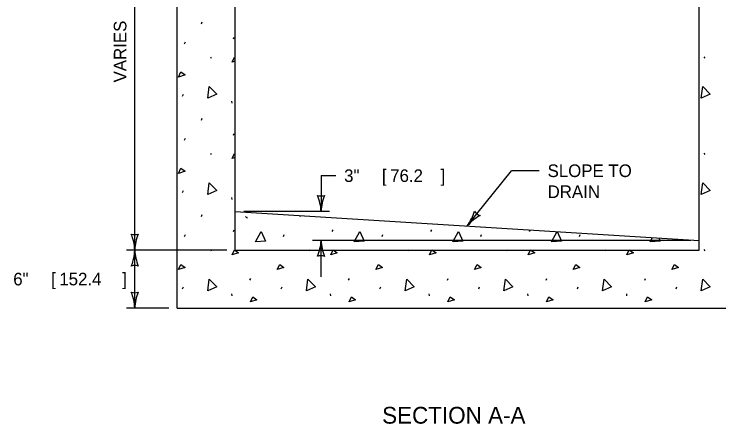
# Model space of a CAD drawing. Extents: x 49991.4 to 50057, y 49987.6 to 50011.4.
# Drawn here: x 50041.919 to 50045.28, y 49989.082 to 49991.034 of the extents above; entities that cross this region are included whole.
import ezdxf

# ---------------------------------------------------------------- set-up
doc = ezdxf.new("R2010")
doc.units = 0
for name, color, linetype in [('Level 1', 7, 'Continuous'), ('Level 2', 7, 'Continuous'), ('Level 3', 7, 'Continuous')]:
    doc.layers.add(name, color=color, linetype=linetype)

msp = doc.modelspace()

# ---------------------------------------------------------------- linework, layer by layer
at = {"layer": 'Level 1'}
for p, q in [((50042.6975, 49989.6339), (50042.6975, 49992.1229)), ((50042.974, 49989.9104), (50042.974, 49991.8463)), ((50045.1865, 49989.9104), (50045.1865, 49991.8463)), ((50042.8121, 49990.9888), (50042.8161, 49990.9976)), ((50042.7326, 49990.8933), (50042.7365, 49990.9022)), ((50042.9654, 49990.9159), (50042.9693, 49990.9248)), ((50042.8554, 49990.8305), (50042.8593, 49990.8246)), ((50045.2081, 49990.8305), (50045.2121, 49990.8246)), ((50042.974, 49990.8098), (50042.9585, 49990.8049)), ((50042.7228, 49990.6438), (50042.7267, 49990.6527)), ((50042.9563, 49990.6192), (50042.9573, 49990.6103)), ((50042.8121, 49990.5299), (50042.8161, 49990.5387)), ((50042.9654, 49990.4571), (50042.9693, 49990.4659)), ((50042.7326, 49990.4345), (50042.7365, 49990.4433)), ((50042.8554, 49990.3716), (50042.8593, 49990.3657)), ((50045.2081, 49990.3716), (50045.2121, 49990.3657)), ((50042.974, 49990.3509), (50042.9585, 49990.3461)), ((50042.7228, 49990.185), (50042.7267, 49990.1938)), ((50042.9563, 49990.1603), (50042.9573, 49990.1514)), ((50042.974, 49990.0948), (50045.1865, 49989.9565)), ((50042.8121, 49990.071), (50042.8161, 49990.0799)), ((50043.0234, 49990.071), (50043.0273, 49990.0651)), ((50043.0273, 49990.0688), (50043.0312, 49990.0629)), ((50043.2827, 49990.071), (50043.2846, 49990.0754)), ((50042.9654, 49989.9982), (50042.9693, 49990.007)), ((50043.4359, 49989.9982), (50043.4399, 49990.007)), ((50043.9065, 49989.9982), (50043.9104, 49990.007)), ((50044.3771, 49989.9982), (50044.3809, 49990.0069)), ((50044.4822, 49989.9491), (50044.5086, 49989.9989)), ((50042.7326, 49989.9756), (50042.7365, 49989.9844)), ((50043.2031, 49989.9756), (50043.2071, 49989.9844)), ((50043.6737, 49989.9756), (50043.6776, 49989.9844)), ((50044.1442, 49989.9756), (50044.1482, 49989.9844)), ((50044.6148, 49989.9756), (50044.6187, 49989.9844)), ((50044.9527, 49989.9491), (50044.964, 49989.9704)), ((50042.8554, 49989.9127), (50042.8593, 49989.9068)), ((50042.974, 49989.9104), (50045.1865, 49989.9104)), ((50043.3259, 49989.9127), (50043.3299, 49989.9068)), ((50043.7965, 49989.9127), (50043.8004, 49989.9068)), ((50044.267, 49989.9127), (50044.271, 49989.9068)), ((50044.7376, 49989.9127), (50044.7415, 49989.9068)), ((50045.2081, 49989.9127), (50045.2121, 49989.9068)), ((50043.044, 49989.7664), (50043.0479, 49989.7752)), ((50043.5145, 49989.7664), (50043.5185, 49989.7752)), ((50043.9851, 49989.7664), (50043.989, 49989.7752)), ((50044.4557, 49989.7664), (50044.4596, 49989.7752)), ((50044.9262, 49989.7664), (50044.9301, 49989.7752)), ((50042.7228, 49989.7261), (50042.7267, 49989.7349)), ((50043.1933, 49989.7261), (50043.1972, 49989.7349)), ((50043.6639, 49989.7261), (50043.6678, 49989.7349)), ((50044.1344, 49989.7261), (50044.1383, 49989.7349)), ((50044.605, 49989.7261), (50044.6089, 49989.7349)), ((50045.0755, 49989.7261), (50045.0795, 49989.7349)), ((50042.9563, 49989.7014), (50042.9573, 49989.6926)), ((50043.4269, 49989.7014), (50043.4278, 49989.6926)), ((50043.8974, 49989.7014), (50043.8984, 49989.6926)), ((50044.368, 49989.7014), (50044.369, 49989.6926)), ((50044.8385, 49989.7014), (50044.8395, 49989.6926)), ((50042.6975, 49989.6339), (50045.463, 49989.6339))]:
    msp.add_line(p, q, dxfattribs=at)
for points in [[(50042.9585, 49990.8049), (50042.9703, 49990.8295), (50042.974, 49990.8267)], [(50042.7033, 49990.7347), (50042.7151, 49990.7593), (50042.7347, 49990.7445), (50042.7033, 49990.7347)], [(50042.8423, 49990.6337), (50042.8501, 49990.6898), (50042.8852, 49990.6535), (50042.8432, 49990.634)], [(50045.195, 49990.6337), (50045.2028, 49990.6898), (50045.238, 49990.6535), (50045.196, 49990.634)], [(50042.9585, 49990.3461), (50042.9703, 49990.3706), (50042.974, 49990.3678)], [(50042.7033, 49990.2758), (50042.7151, 49990.3004), (50042.7347, 49990.2857), (50042.7033, 49990.2758)], [(50042.8423, 49990.1748), (50042.8501, 49990.2309), (50042.8852, 49990.1946), (50042.8432, 49990.1751)], [(50045.195, 49990.1748), (50045.2028, 49990.2309), (50045.238, 49990.1946), (50045.196, 49990.1751)], [(50043.0705, 49989.9491), (50043.097, 49989.9992), (50043.1177, 49989.953), (50043.0715, 49989.9491)], [(50043.5411, 49989.9491), (50043.5676, 49989.9992), (50043.5882, 49989.953), (50043.5421, 49989.9491)], [(50044.0116, 49989.9491), (50044.0381, 49989.9992), (50044.0588, 49989.953), (50044.0126, 49989.9491)], [(50044.5088, 49989.9989), (50044.5293, 49989.953), (50044.4832, 49989.9491)], [(50044.9929, 49989.9686), (50044.9999, 49989.953), (50044.9537, 49989.9491)], [(50042.9585, 49989.8872), (50042.9703, 49989.9117), (50042.9899, 49989.897), (50042.9585, 49989.8872)], [(50043.4291, 49989.8872), (50043.4409, 49989.9117), (50043.4605, 49989.897), (50043.4291, 49989.8872)], [(50043.8996, 49989.8872), (50043.9114, 49989.9117), (50043.9311, 49989.897), (50043.8996, 49989.8872)], [(50044.3702, 49989.8872), (50044.382, 49989.9117), (50044.4016, 49989.897), (50044.3702, 49989.8872)], [(50044.8407, 49989.8872), (50044.8525, 49989.9117), (50044.8722, 49989.897), (50044.8407, 49989.8872)], [(50042.7033, 49989.817), (50042.7151, 49989.8415), (50042.7347, 49989.8268), (50042.7033, 49989.817)], [(50043.1739, 49989.817), (50043.1856, 49989.8415), (50043.2053, 49989.8268), (50043.1739, 49989.817)], [(50043.6444, 49989.817), (50043.6562, 49989.8415), (50043.6758, 49989.8268), (50043.6444, 49989.817)], [(50044.115, 49989.817), (50044.1268, 49989.8415), (50044.1464, 49989.8268), (50044.115, 49989.817)], [(50044.5855, 49989.817), (50044.5973, 49989.8415), (50044.617, 49989.8268), (50044.5855, 49989.817)], [(50045.0561, 49989.817), (50045.0679, 49989.8415), (50045.0875, 49989.8268), (50045.0561, 49989.817)], [(50042.8423, 49989.7159), (50042.8501, 49989.7721), (50042.8852, 49989.7357), (50042.8432, 49989.7163)], [(50043.3128, 49989.7159), (50043.3206, 49989.7721), (50043.3558, 49989.7357), (50043.3137, 49989.7163)], [(50043.7834, 49989.7159), (50043.7912, 49989.7721), (50043.8263, 49989.7357), (50043.7843, 49989.7163)], [(50044.2539, 49989.7159), (50044.2617, 49989.7721), (50044.2969, 49989.7357), (50044.2548, 49989.7163)], [(50044.7245, 49989.7159), (50044.7323, 49989.7721), (50044.7674, 49989.7357), (50044.7254, 49989.7163)], [(50045.195, 49989.7159), (50045.2028, 49989.7721), (50045.238, 49989.7357), (50045.196, 49989.7163)], [(50043.046, 49989.6632), (50043.0577, 49989.6878), (50043.0774, 49989.673), (50043.046, 49989.6632)], [(50043.5165, 49989.6632), (50043.5283, 49989.6878), (50043.5479, 49989.673), (50043.5165, 49989.6632)], [(50043.9871, 49989.6632), (50043.9989, 49989.6878), (50044.0185, 49989.673), (50043.9871, 49989.6632)], [(50044.4576, 49989.6632), (50044.4694, 49989.6878), (50044.4891, 49989.673), (50044.4576, 49989.6632)], [(50044.9282, 49989.6632), (50044.94, 49989.6878), (50044.9596, 49989.673), (50044.9282, 49989.6632)]]:
    msp.add_lwpolyline(points, dxfattribs=at)
at = {"layer": 'Level 3'}
for p, q in [((50042.4948, 49989.9104), (50042.4948, 49991.4606)), ((50044.0803, 49990.0257), (50044.2903, 49990.2882)), ((50044.4231, 49990.2882), (50044.2903, 49990.2882)), ((50043.3829, 49990.2648), (50043.3829, 49990.0948)), ((50043.3829, 49990.2648), (50043.4529, 49990.2648)), ((50043.4229, 49990.0948), (50043.014, 49990.0948)), ((50045.1465, 49989.9565), (50043.3429, 49989.9565)), ((50043.3829, 49989.7831), (50043.3829, 49989.9565)), ((50042.934, 49989.9104), (50042.4548, 49989.9104)), ((50042.4948, 49989.6339), (50042.4948, 49989.9104)), ((50042.6575, 49989.6339), (50042.4548, 49989.6339))]:
    msp.add_line(p, q, dxfattribs=at)
for centre, radius, start, end in [((50043.3829, 49990.223), 0.0548, 252.1388, 287.8612), ((50043.1502, 49990.0833), 0.233, 2.8273, 22.0772), ((50043.6051, 49990.0856), 0.2223, 157.456, 177.6395), ((50043.8914, 49990.1621), 0.233, 324.1595, 343.4094), ((50044.1604, 49990.1258), 0.0548, 213.471, 249.1934), ((50044.248, 49989.8797), 0.2223, 118.7882, 138.9717), ((50042.4948, 49990.0386), 0.0548, 252.1388, 287.8612), ((50042.2621, 49989.8989), 0.233, 2.8273, 22.0772), ((50042.7169, 49989.9013), 0.2223, 157.456, 177.6395), ((50043.1608, 49989.9657), 0.2223, 337.456, 357.6395), ((50043.6156, 49989.968), 0.233, 182.8273, 202.0772), ((50042.2727, 49989.9196), 0.2223, 337.456, 357.6395), ((50042.7275, 49989.9219), 0.233, 182.8273, 202.0772), ((50043.3829, 49989.8283), 0.0548, 72.1388, 107.8612), ((50042.4948, 49989.7822), 0.0548, 72.1388, 107.8612), ((50042.4948, 49989.7621), 0.0548, 252.1388, 287.8612), ((50042.2621, 49989.6224), 0.233, 2.8273, 22.0772), ((50042.7169, 49989.6247), 0.2223, 157.456, 177.6395)]:
    msp.add_arc(centre, radius, start, end, dxfattribs=at)

# ---------------------------------------------------------------- texts
at = {"layer": 'Level 2'}
for s, rotation, p in [('VARIES', 90, (50042.4548, 49990.7089)), ('3" ', 360, (50043.4929, 49990.2348)), ('[', 360, (50043.6729, 49990.2348)), ('76.2', 360, (50043.7126, 49990.2348)), (']', 360, (50043.9526, 49990.2348))]:
    msp.add_text(s, height=0.06, rotation=rotation, dxfattribs=at).set_placement(p)
for s, height, p in [('SLOPE TO ', 0.06, (50044.4631, 49990.2582)), ('DRAIN', 0.06, (50044.4631, 49990.1582)), ('6" ', 0.06, (50041.9153, 49989.7422)), ('[', 0.06, (50042.0953, 49989.7422)), ('152.4', 0.06, (50042.135, 49989.7422)), (']', 0.06, (50042.435, 49989.7422)), ('SECTION A-A', 0.08, (50043.6741, 49989.0834))]:
    msp.add_text(s, height=height, dxfattribs=at).set_placement(p)

doc.saveas('drawing.dxf')
